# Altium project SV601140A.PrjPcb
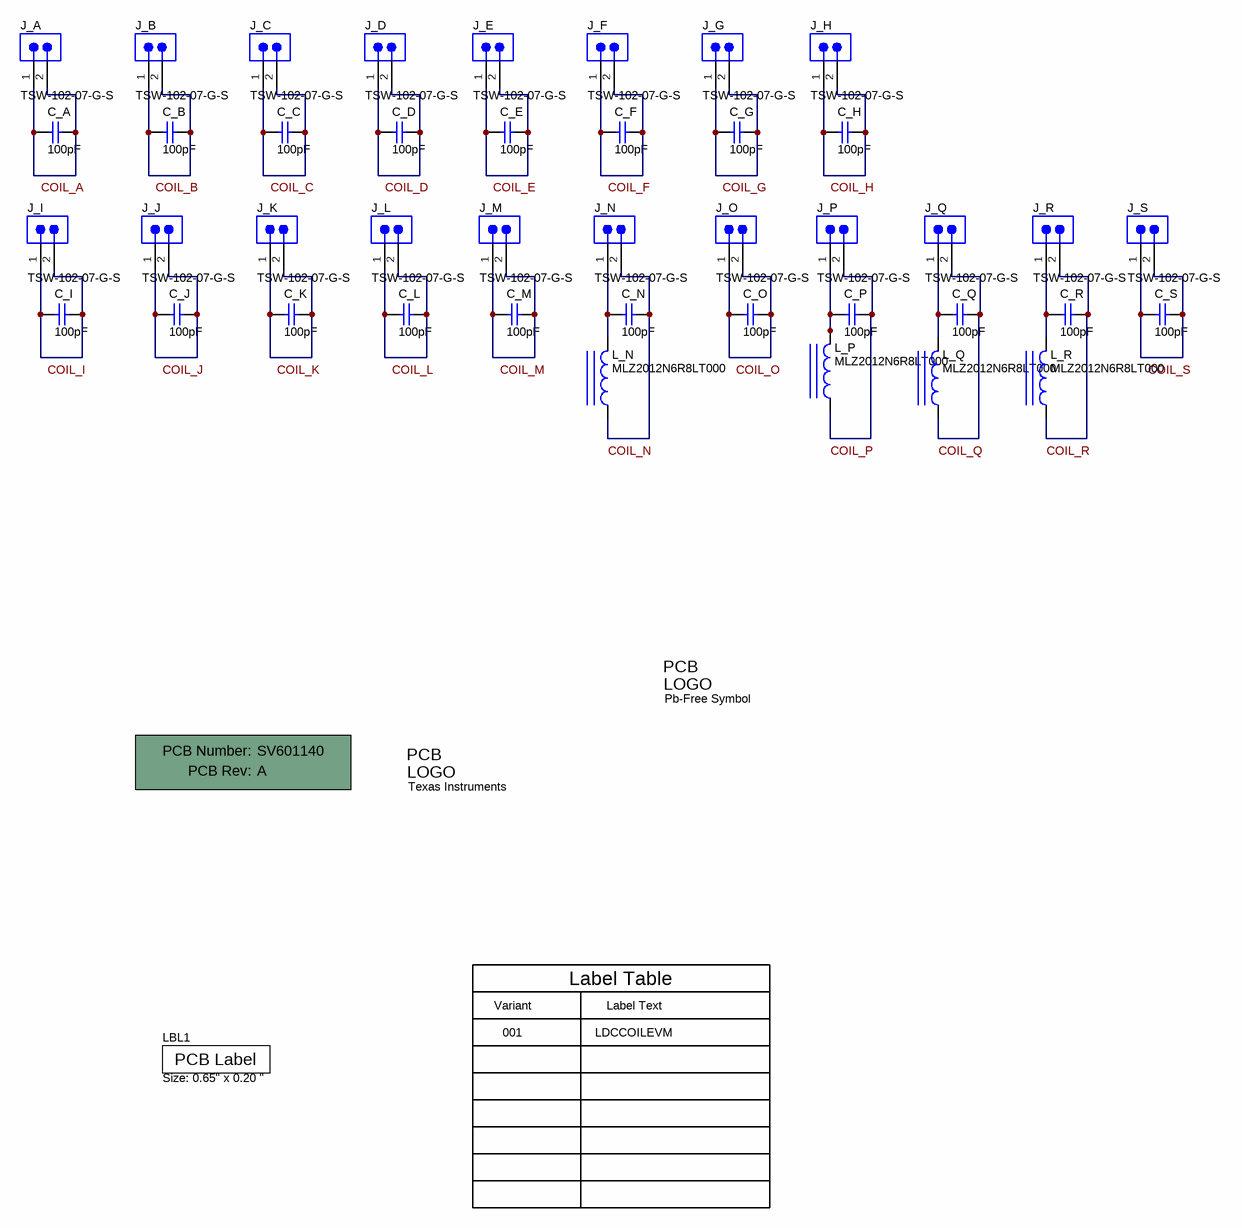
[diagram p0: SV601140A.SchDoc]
CopyrightYear: 2014; PCB_Layout: Ben Kasemsadeh; PCB_Rev: A; PRJ_Customer: Public Release; PRJ_Engineer: Ben Kasemsadeh; PRJ_Number: SV601140; PRJ_Title: LDCCOILEVM; SCH_Rev: A; TechSupport: http://www.ti.com/support
1 sheet, 46 parts. Net scope: global (net labels, ports and power ports of the same name join across sheets).
Board file: SV601140A.PcbDoc

## Sheet SV601140A.SchDoc
size 431 x 279 mm; Date: Not shown in title block; ApprovedBy: Not shown in title block; CheckedBy: Not shown in title block; Author: Not shown in title block; CompanyName: Not shown in title block; Engineer: Not shown in title block; Organization: Not shown in title block; Address1: Not shown in title block; Address2: Not shown in title block; Address3: Not shown in title block; Address4: Not shown in title block; DocumentNumber: 1; Revision: Use project parameter SCH_Rev; SheetNumber: 1; SheetTotal: 1; PageSetup: Record=PageOptions¦CenterHorizontal=True¦CenterVertical=True¦PrintScale=1.00¦XCorrection=1.00¦YCorrection=1.00¦PrintKind=0¦BorderSize=5000000¦LeftOffset=0¦BottomOffset=0¦Orientation=2¦PaperLength=1000¦PaperWidth=1000¦Scale=100¦PaperSource=15¦PrintQuality=600¦MediaType=1¦DitherType=10¦PaperKind=Letter¦PrintScaleMode=1

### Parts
!PCB  Printed Circuit Board  (value not drawn)  (mechanical)
C_A  ValueDisplayed: 100pF  [0603]  (hidden comment: 06035A101FAT2A)
C_B  ValueDisplayed: 100pF  [0603]  (hidden comment: 06035A101FAT2A)
C_C  ValueDisplayed: 100pF  [0603]  (hidden comment: 06035A101FAT2A)
C_D  ValueDisplayed: 100pF  [0603]  (hidden comment: 06035A101FAT2A)
C_E  ValueDisplayed: 100pF  [0603]  (hidden comment: 06035A101FAT2A)
C_F  ValueDisplayed: 100pF  [0603]  (hidden comment: 06035A101FAT2A)
C_G  ValueDisplayed: 100pF  [0603]  (hidden comment: 06035A101FAT2A)
C_H  ValueDisplayed: 100pF  [0603]  (hidden comment: 06035A101FAT2A)
C_I  ValueDisplayed: 100pF  [0603]  (hidden comment: 06035A101FAT2A)
C_J  ValueDisplayed: 100pF  [0603]  (hidden comment: 06035A101FAT2A)
C_K  ValueDisplayed: 100pF  [0603]  (hidden comment: 06035A101FAT2A)
C_L  ValueDisplayed: 100pF  [0603]  (hidden comment: 06035A101FAT2A)
C_M  ValueDisplayed: 100pF  [0603]  (hidden comment: 06035A101FAT2A)
C_N  ValueDisplayed: 100pF  [0603]  (hidden comment: 06035A101FAT2A)
C_O  ValueDisplayed: 100pF  [0603]  (hidden comment: 06035A101FAT2A)
C_P  ValueDisplayed: 100pF  [0603]  (hidden comment: 06035A101FAT2A)
C_Q  ValueDisplayed: 100pF  [0603]  (hidden comment: 06035A101FAT2A)
C_R  ValueDisplayed: 100pF  [0603]  (hidden comment: 06035A101FAT2A)
C_S  ValueDisplayed: 100pF  [0603]  (hidden comment: 06035A101FAT2A)
J_A  TSW-102-07-G-S  [TSW-102-07-G-S]
J_B  TSW-102-07-G-S  [TSW-102-07-G-S]
J_C  TSW-102-07-G-S  [TSW-102-07-G-S]
J_D  TSW-102-07-G-S  [TSW-102-07-G-S]
J_E  TSW-102-07-G-S  [TSW-102-07-G-S]
J_F  TSW-102-07-G-S  [TSW-102-07-G-S]
J_G  TSW-102-07-G-S  [TSW-102-07-G-S]
J_H  TSW-102-07-G-S  [TSW-102-07-G-S]
J_I  TSW-102-07-G-S  [TSW-102-07-G-S]
J_J  TSW-102-07-G-S  [TSW-102-07-G-S]
J_K  TSW-102-07-G-S  [TSW-102-07-G-S]
J_L  TSW-102-07-G-S  [TSW-102-07-G-S]
J_M  TSW-102-07-G-S  [TSW-102-07-G-S]
J_N  TSW-102-07-G-S  [TSW-102-07-G-S]
J_O  TSW-102-07-G-S  [TSW-102-07-G-S]
J_P  TSW-102-07-G-S  [TSW-102-07-G-S]
J_Q  TSW-102-07-G-S  [TSW-102-07-G-S]
J_R  TSW-102-07-G-S  [TSW-102-07-G-S]
J_S  TSW-102-07-G-S  [TSW-102-07-G-S]
L_N  MLZ2012N6R8LT000  [0805_145]
L_P  MLZ2012N6R8LT000  [0805_145]
L_Q  MLZ2012N6R8LT000  [0805_145]
L_R  MLZ2012N6R8LT000  [0805_145]
LBL1  Size: 0.65" x 0.20 "  [Label_650x200]
Logo1  Texas Instruments  [TI_Stacked_SolderMask_Small]  (no BOM)
Logo?  Pb-Free Symbol  [Pb-Free_Overlay_Medium]  (no BOM)

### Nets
NetC_A_1: C_A.1 C_A.2 J_A.1 J_A.2
NetC_B_1: C_B.1 C_B.2 J_B.1 J_B.2
NetC_C_1: C_C.1 C_C.2 J_C.1 J_C.2
NetC_D_1: C_D.1 C_D.2 J_D.1 J_D.2
NetC_E_1: C_E.1 C_E.2 J_E.1 J_E.2
NetC_F_1: C_F.1 C_F.2 J_F.1 J_F.2
NetC_G_1: C_G.1 C_G.2 J_G.1 J_G.2
NetC_H_1: C_H.1 C_H.2 J_H.1 J_H.2
NetC_I_1: C_I.1 C_I.2 J_I.1 J_I.2
NetC_J_1: C_J.1 C_J.2 J_J.1 J_J.2
NetC_K_1: C_K.1 C_K.2 J_K.1 J_K.2
NetC_L_1: C_L.1 C_L.2 J_L.1 J_L.2
NetC_M_1: C_M.1 C_M.2 J_M.1 J_M.2
NetC_N_1: C_N.1 J_N.1 L_N.2
NetC_N_2: C_N.2 J_N.2 L_N.1
NetC_O_1: C_O.1 C_O.2 J_O.1 J_O.2
NetC_P_1: C_P.1 J_P.1 L_P.2
NetC_P_2: C_P.2 J_P.2 L_P.1
NetC_Q_1: C_Q.1 J_Q.1 L_Q.2
NetC_Q_2: C_Q.2 J_Q.2 L_Q.1
NetC_R_1: C_R.1 J_R.1 L_R.2
NetC_R_2: C_R.2 J_R.2 L_R.1
NetC_S_1: C_S.1 C_S.2 J_S.1 J_S.2

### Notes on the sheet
- Variant
- Label Table
- Label Text
- 001
- LDCCOILEVM
- Labels drawn without touching a wire or pin: COIL_A, COIL_B, COIL_C, COIL_D, COIL_E, COIL_F, COIL_G, COIL_H, COIL_I, COIL_J, COIL_K, COIL_L, COIL_M, COIL_N, COIL_O, COIL_P, COIL_Q, COIL_R, COIL_S

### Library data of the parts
!PCB = PCB: Manufacturer: Any; PartNumber: SV601140; SymbolCreator: a0412235
C_A C_B C_C C_D C_E C_F C_G C_H C_I C_J C_K C_L C_M C_N C_O C_P C_Q C_R C_S = GRM1885C2A300JA01D: CAP CER 100PF 50V 1% NP0 0603; Manufacturer: AVX Corporation; Polarized: N; CompType: Capacitor; U/M: EA; Cap_F: 0.00000000003; Tolerance_%: 5; VDC_V: 100; Value2: 100V; TempCo: C0G/NP0; TaMin_C: -55; TaMax_C: 125
J_A J_B J_C J_D J_E J_F J_G J_H J_I J_J J_K J_L J_M J_N J_O J_P J_Q J_R J_S = TSW-102-07-G-S: Header, TH, 100mil, 2x1, Gold plated, 230 mil above insulator; Manufacturer: Samtec, Inc.; SymbolCreator: a0412235; U/M: EA
L_N L_P L_Q L_R = MLZ2012N6R8LT000: Inductor, Multilayer, Ferrite, 6.8 µH, 0.11 A, 0.25 ohm, SMD; Manufacturer: TDK; Value: 6.8uH; Ind_H: 6.8E-6; ValueDisplayed: 6.8µH; Imax_A: 0.11; Irms: 0.55A @ 20C rise; Isat: 0.11A @ 50% inductance drop; DCR_ohm: 0.25; Value2: 0.11A
LBL1 = THT-14-423-10: Thermal Transfer Printable Labels, 0.650" W x 0.200" H - 10,000 per roll; Manufacturer: Brady; SymbolCreator: a0412235; CompType: Label
Logo1 = TI_Logo: Texas Instrument Corporate Signature; SymbolCreator: codlsc
Logo? = Pb-Free: SymbolCreator: a0412235

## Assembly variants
001: not fitted C_A C_B C_C C_D C_E C_F C_G C_H C_I C_J C_K C_L C_M C_N C_O C_P C_Q C_R C_S FID1 FID2 FID3 J_A J_B J_C J_D J_E J_F J_G J_H J_I J_J J_K J_L J_M J_N J_O J_P J_Q J_R J_S L_N L_P L_Q L_R LBL1 Logo1 Logo?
